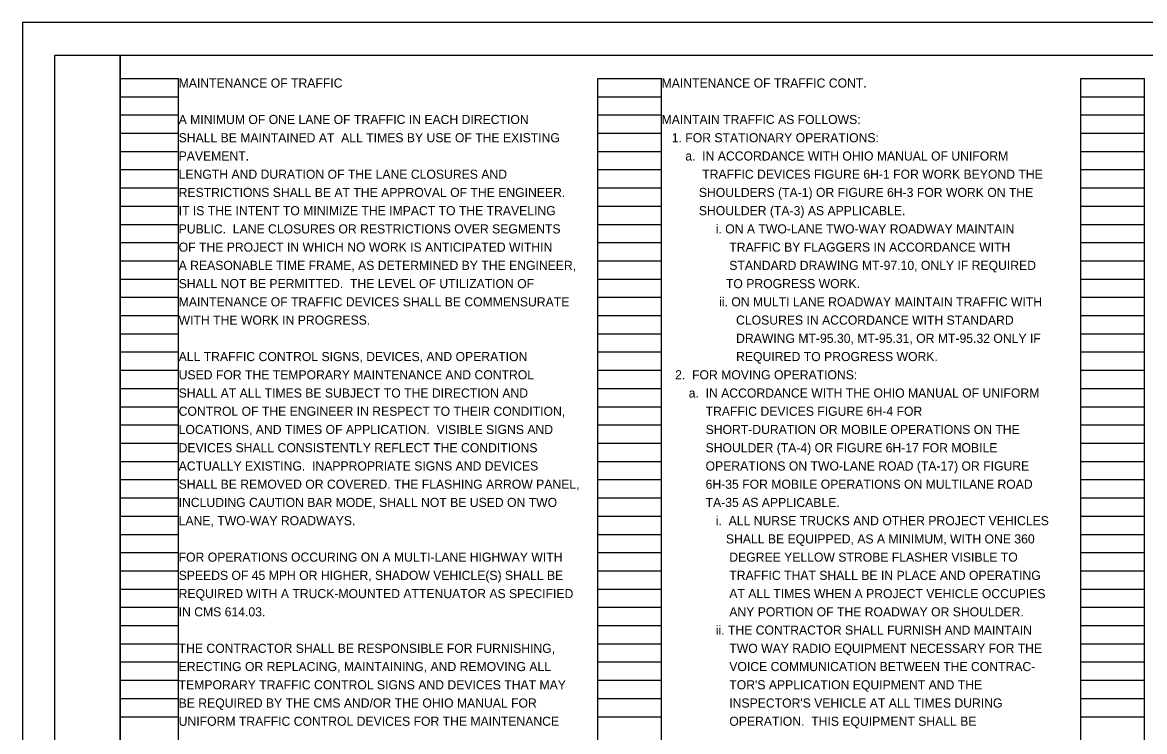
# Model space of a CAD drawing. Extents: x 0 to 34, y 0 to 22.
# Drawn here: x 0 to 17.24, y 11.11 to 22 of the extents above; entities that cross this region are included whole.
import ezdxf

# ---------------------------------------------------------------- set-up
doc = ezdxf.new("R2010")
doc.units = 0
for name, color, linetype in [('SH_Border', 7, 'Continuous'), ('SH_Cut_Line', 7, 'Continuous'), ('SH_Data', 7, 'Continuous'), ('SH_Text', 7, 'Continuous')]:
    doc.layers.add(name, color=color, linetype=linetype)

msp = doc.modelspace()

# ---------------------------------------------------------------- linework, layer by layer
at = {"layer": 'SH_Border'}
for points in [[(0.5, 21.5), (1.5, 21.5), (1.5, 0.5), (0.5, 0.5)], [(1.5, 21.5), (33.5, 21.5), (33.5, 0.5), (1.5, 0.5)]]:
    msp.add_lwpolyline(points, close=True, dxfattribs=at)
at = {"layer": 'SH_Cut_Line'}
msp.add_lwpolyline([(0, 0), (34, 0), (34, 22), (0, 22)], close=True, dxfattribs=at)
at = {"layer": 'SH_Data'}
for p, q in [((1.5, 0.98), (1.5, 21.14)), ((1.5, 21.14), (2.4, 21.14)), ((2.4, 0.98), (2.4, 21.14)), ((8.84, 0.98), (8.84, 21.14)), ((8.84, 21.14), (9.82, 21.14)), ((9.82, 0.98), (9.82, 21.14)), ((16.26, 0.98), (16.26, 21.14)), ((16.26, 21.14), (17.24, 21.14)), ((17.24, 0.98), (17.24, 21.14)), ((1.5, 20.86), (2.4, 20.86)), ((8.84, 20.86), (9.82, 20.86)), ((16.26, 20.86), (17.24, 20.86)), ((1.5, 20.58), (2.4, 20.58)), ((8.84, 20.58), (9.82, 20.58)), ((16.26, 20.58), (17.24, 20.58)), ((1.5, 20.3), (2.4, 20.3)), ((8.84, 20.3), (9.82, 20.3)), ((16.26, 20.3), (17.24, 20.3)), ((1.5, 20.02), (2.4, 20.02)), ((8.84, 20.02), (9.82, 20.02)), ((16.26, 20.02), (17.24, 20.02)), ((1.5, 19.74), (2.4, 19.74)), ((8.84, 19.74), (9.82, 19.74)), ((16.26, 19.74), (17.24, 19.74)), ((1.5, 19.46), (2.4, 19.46)), ((8.84, 19.46), (9.82, 19.46)), ((16.26, 19.46), (17.24, 19.46)), ((1.5, 19.18), (2.4, 19.18)), ((8.84, 19.18), (9.82, 19.18)), ((16.26, 19.18), (17.24, 19.18)), ((1.5, 18.9), (2.4, 18.9)), ((8.84, 18.9), (9.82, 18.9)), ((16.26, 18.9), (17.24, 18.9)), ((1.5, 18.62), (2.4, 18.62)), ((8.84, 18.62), (9.82, 18.62)), ((16.26, 18.62), (17.24, 18.62)), ((1.5, 18.34), (2.4, 18.34)), ((8.84, 18.34), (9.82, 18.34)), ((16.26, 18.34), (17.24, 18.34)), ((1.5, 18.06), (2.4, 18.06)), ((8.84, 18.06), (9.82, 18.06)), ((16.26, 18.06), (17.24, 18.06)), ((1.5, 17.78), (2.4, 17.78)), ((8.84, 17.78), (9.82, 17.78)), ((16.26, 17.78), (17.24, 17.78)), ((1.5, 17.5), (2.4, 17.5)), ((8.84, 17.5), (9.82, 17.5)), ((16.26, 17.5), (17.24, 17.5)), ((1.5, 17.22), (2.4, 17.22)), ((8.84, 17.22), (9.82, 17.22)), ((16.26, 17.22), (17.24, 17.22)), ((1.5, 16.94), (2.4, 16.94)), ((8.84, 16.94), (9.82, 16.94)), ((16.26, 16.94), (17.24, 16.94)), ((1.5, 16.66), (2.4, 16.66)), ((8.84, 16.66), (9.82, 16.66)), ((16.26, 16.66), (17.24, 16.66)), ((1.5, 16.38), (2.4, 16.38)), ((8.84, 16.38), (9.82, 16.38)), ((16.26, 16.38), (17.24, 16.38)), ((1.5, 16.1), (2.4, 16.1)), ((8.84, 16.1), (9.82, 16.1)), ((16.26, 16.1), (17.24, 16.1)), ((1.5, 15.82), (2.4, 15.82)), ((8.84, 15.82), (9.82, 15.82)), ((16.26, 15.82), (17.24, 15.82)), ((1.5, 15.54), (2.4, 15.54)), ((8.84, 15.54), (9.82, 15.54)), ((16.26, 15.54), (17.24, 15.54)), ((1.5, 15.26), (2.4, 15.26)), ((8.84, 15.26), (9.82, 15.26)), ((16.26, 15.26), (17.24, 15.26)), ((1.5, 14.98), (2.4, 14.98)), ((8.84, 14.98), (9.82, 14.98)), ((16.26, 14.98), (17.24, 14.98)), ((1.5, 14.7), (2.4, 14.7)), ((8.84, 14.7), (9.82, 14.7)), ((16.26, 14.7), (17.24, 14.7)), ((1.5, 14.42), (2.4, 14.42)), ((8.84, 14.42), (9.82, 14.42)), ((16.26, 14.42), (17.24, 14.42)), ((1.5, 14.14), (2.4, 14.14)), ((8.84, 14.14), (9.82, 14.14)), ((16.26, 14.14), (17.24, 14.14)), ((1.5, 13.86), (2.4, 13.86)), ((8.84, 13.86), (9.82, 13.86)), ((16.26, 13.86), (17.24, 13.86)), ((1.5, 13.58), (2.4, 13.58)), ((8.84, 13.58), (9.82, 13.58)), ((16.26, 13.58), (17.24, 13.58)), ((1.5, 13.3), (2.4, 13.3)), ((8.84, 13.3), (9.82, 13.3)), ((16.26, 13.3), (17.24, 13.3)), ((1.5, 13.02), (2.4, 13.02)), ((8.84, 13.02), (9.82, 13.02)), ((16.26, 13.02), (17.24, 13.02)), ((1.5, 12.74), (2.4, 12.74)), ((8.84, 12.74), (9.82, 12.74)), ((16.26, 12.74), (17.24, 12.74)), ((1.5, 12.46), (2.4, 12.46)), ((8.84, 12.46), (9.82, 12.46)), ((16.26, 12.46), (17.24, 12.46)), ((1.5, 12.18), (2.4, 12.18)), ((8.84, 12.18), (9.82, 12.18)), ((16.26, 12.18), (17.24, 12.18)), ((1.5, 11.9), (2.4, 11.9)), ((8.84, 11.9), (9.82, 11.9)), ((16.26, 11.9), (17.24, 11.9)), ((1.5, 11.62), (2.4, 11.62)), ((8.84, 11.62), (9.82, 11.62)), ((16.26, 11.62), (17.24, 11.62)), ((1.5, 11.34), (2.4, 11.34)), ((8.84, 11.34), (9.82, 11.34)), ((16.26, 11.34), (17.24, 11.34))]:
    msp.add_line(p, q, dxfattribs=at)

# ---------------------------------------------------------------- texts
at = {"layer": 'SH_Text'}
for s, p in [('MAINTENANCE OF TRAFFIC', (2.4, 21)), ('MAINTENANCE OF TRAFFIC CONT.', (9.82, 21)), ('A MINIMUM OF ONE LANE OF TRAFFIC IN EACH DIRECTION ', (2.4, 20.44)), ('MAINTAIN TRAFFIC AS FOLLOWS:', (9.82, 20.44)), ('SHALL BE MAINTAINED AT  ALL TIMES BY USE OF THE EXISTING ', (2.4, 20.16)), ('   1. FOR STATIONARY OPERATIONS:', (9.82, 20.16)), ('PAVEMENT.', (2.4, 19.88)), ('       a.  IN ACCORDANCE WITH OHIO MANUAL OF UNIFORM      ', (9.82, 19.88)), ('LENGTH AND DURATION OF THE LANE CLOSURES AND ', (2.4, 19.6)), ('            TRAFFIC DEVICES FIGURE 6H-1 FOR WORK BEYOND THE', (9.82, 19.6)), ('RESTRICTIONS SHALL BE AT THE APPROVAL OF THE ENGINEER.', (2.4, 19.32)), ('           SHOULDERS (TA-1) OR FIGURE 6H-3 FOR WORK ON THE ', (9.82, 19.32)), ('IT IS THE INTENT TO MINIMIZE THE IMPACT TO THE TRAVELING', (2.4, 19.04)), ('           SHOULDER (TA-3) AS APPLICABLE.', (9.82, 19.04)), ('PUBLIC.  LANE CLOSURES OR RESTRICTIONS OVER SEGMENTS ', (2.4, 18.76)), ('                i. ON A TWO-LANE TWO-WAY ROADWAY MAINTAIN ', (9.82, 18.76)), ('OF THE PROJECT IN WHICH NO WORK IS ANTICIPATED WITHIN', (2.4, 18.48)), ('                    TRAFFIC BY FLAGGERS IN ACCORDANCE WITH ', (9.82, 18.48)), ('A REASONABLE TIME FRAME, AS DETERMINED BY THE ENGINEER, ', (2.4, 18.2)), ('                    STANDARD DRAWING MT-97.10, ONLY IF REQUIRED', (9.82, 18.2)), ('SHALL NOT BE PERMITTED.  THE LEVEL OF UTILIZATION OF', (2.4, 17.92)), ('                   TO PROGRESS WORK.', (9.82, 17.92)), ('MAINTENANCE OF TRAFFIC DEVICES SHALL BE COMMENSURATE ', (2.4, 17.64)), ('                 ii. ON MULTI LANE ROADWAY MAINTAIN TRAFFIC WITH', (9.82, 17.64)), ('WITH THE WORK IN PROGRESS.', (2.4, 17.36)), ('                      CLOSURES IN ACCORDANCE WITH STANDARD ', (9.82, 17.36)), ('                      DRAWING MT-95.30, MT-95.31, OR MT-95.32 ONLY IF', (9.82, 17.08)), ('ALL TRAFFIC CONTROL SIGNS, DEVICES, AND OPERATION', (2.4, 16.8)), ('                      REQUIRED TO PROGRESS WORK.', (9.82, 16.8)), ('USED FOR THE TEMPORARY MAINTENANCE AND CONTROL', (2.4, 16.52)), ('    2.  FOR MOVING OPERATIONS:', (9.82, 16.52)), ('SHALL AT ALL TIMES BE SUBJECT TO THE DIRECTION AND ', (2.4, 16.24)), ('        a.  IN ACCORDANCE WITH THE OHIO MANUAL OF UNIFORM', (9.82, 16.24)), ('CONTROL OF THE ENGINEER IN RESPECT TO THEIR CONDITION,', (2.4, 15.96)), ('             TRAFFIC DEVICES FIGURE 6H-4 FOR ', (9.82, 15.96)), ('LOCATIONS, AND TIMES OF APPLICATION.  VISIBLE SIGNS AND ', (2.4, 15.68)), ('             SHORT-DURATION OR MOBILE OPERATIONS ON THE ', (9.82, 15.68)), ('DEVICES SHALL CONSISTENTLY REFLECT THE CONDITIONS ', (2.4, 15.4)), ('             SHOULDER (TA-4) OR FIGURE 6H-17 FOR MOBILE', (9.82, 15.4)), ('ACTUALLY EXISTING.  INAPPROPRIATE SIGNS AND DEVICES ', (2.4, 15.12)), ('             OPERATIONS ON TWO-LANE ROAD (TA-17) OR FIGURE ', (9.82, 15.12)), ('SHALL BE REMOVED OR COVERED. THE FLASHING ARROW PANEL,', (2.4, 14.84)), ('             6H-35 FOR MOBILE OPERATIONS ON MULTILANE ROAD ', (9.82, 14.84)), ('INCLUDING CAUTION BAR MODE, SHALL NOT BE USED ON TWO', (2.4, 14.56)), ('             TA-35 AS APPLICABLE.', (9.82, 14.56)), ('LANE, TWO-WAY ROADWAYS.', (2.4, 14.28)), ('                i.  ALL NURSE TRUCKS AND OTHER PROJECT VEHICLES ', (9.82, 14.28)), ('                   SHALL BE EQUIPPED, AS A MINIMUM, WITH ONE 360 ', (9.82, 14)), ('FOR OPERATIONS OCCURING ON A MULTI-LANE HIGHWAY WITH', (2.4, 13.72)), ('                    DEGREE YELLOW STROBE FLASHER VISIBLE TO ', (9.82, 13.72)), ('SPEEDS OF 45 MPH OR HIGHER, SHADOW VEHICLE(S) SHALL BE', (2.4, 13.44)), ('                    TRAFFIC THAT SHALL BE IN PLACE AND OPERATING ', (9.82, 13.44)), ('REQUIRED WITH A TRUCK-MOUNTED ATTENUATOR AS SPECIFIED', (2.4, 13.16)), ('                    AT ALL TIMES WHEN A PROJECT VEHICLE OCCUPIES ', (9.82, 13.16)), ('IN CMS 614.03.', (2.4, 12.88)), ('                    ANY PORTION OF THE ROADWAY OR SHOULDER.', (9.82, 12.88)), ('                ii. THE CONTRACTOR SHALL FURNISH AND MAINTAIN ', (9.82, 12.6)), ('THE CONTRACTOR SHALL BE RESPONSIBLE FOR FURNISHING,', (2.4, 12.32)), ('                    TWO WAY RADIO EQUIPMENT NECESSARY FOR THE ', (9.82, 12.32)), ('ERECTING OR REPLACING, MAINTAINING, AND REMOVING ALL', (2.4, 12.04)), ('                    VOICE COMMUNICATION BETWEEN THE CONTRAC-', (9.82, 12.04)), ('TEMPORARY TRAFFIC CONTROL SIGNS AND DEVICES THAT MAY ', (2.4, 11.76)), ("                    TOR'S APPLICATION EQUIPMENT AND THE ", (9.82, 11.76)), ('BE REQUIRED BY THE CMS AND/OR THE OHIO MANUAL FOR ', (2.4, 11.48)), ("                    INSPECTOR'S VEHICLE AT ALL TIMES DURING", (9.82, 11.48)), ('UNIFORM TRAFFIC CONTROL DEVICES FOR THE MAINTENANCE ', (2.4, 11.2)), ('                    OPERATION.  THIS EQUIPMENT SHALL BE ', (9.82, 11.2))]:
    msp.add_text(s, height=0.14, dxfattribs=at).set_placement(p)

doc.saveas('drawing.dxf')
